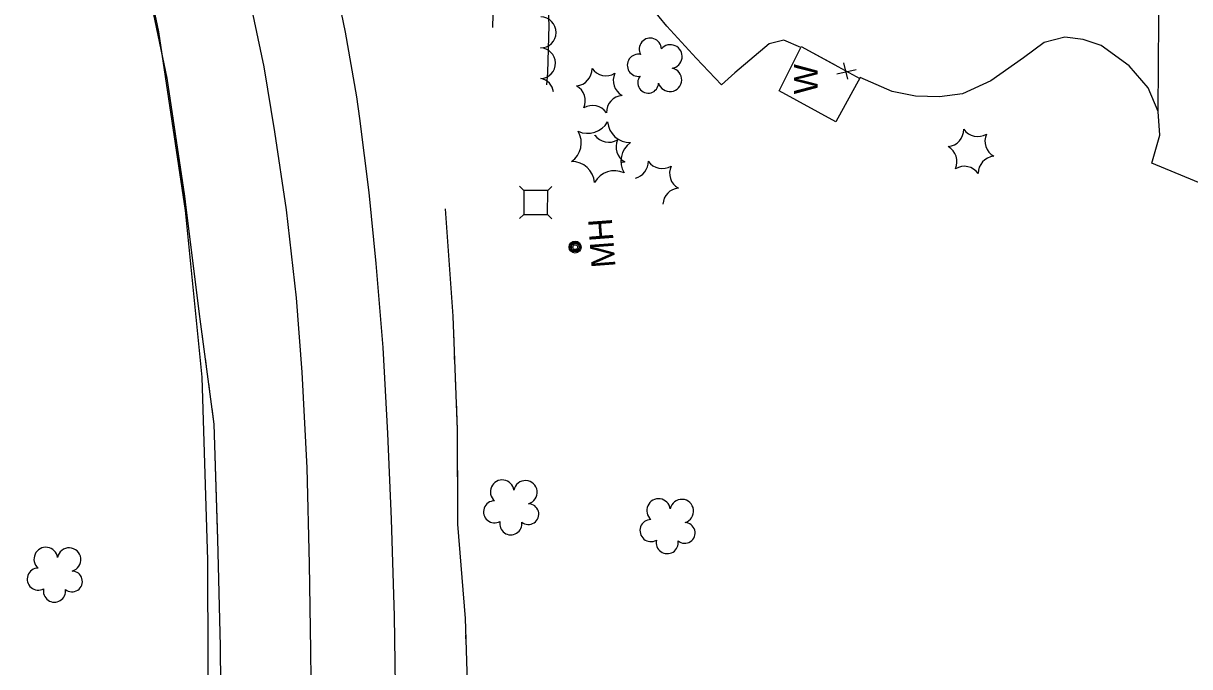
# Model space of a CAD drawing. Extents: x 588843 to 2552415, y 180129 to 269402.
# Drawn here: x 592645.4 to 592938.7, y 185379 to 185540.7 of the extents above; entities that cross this region are included whole.
import ezdxf

# ---------------------------------------------------------------- set-up
doc = ezdxf.new("R2010")
doc.units = 0
for name, color, linetype in [('Level 11', 7, 'Continuous'), ('Level 15', 7, 'Continuous'), ('Level 16', 7, 'Continuous'), ('Level 17', 7, 'Continuous'), ('Level 18', 7, 'Continuous'), ('Level 19', 7, 'Continuous'), ('Level 21', 7, 'Continuous')]:
    doc.layers.add(name, color=color, linetype=linetype)

msp = doc.modelspace()

# ---------------------------------------------------------------- linework, layer by layer
at = {"layer": 'Level 11'}
for points in [[(592682.83, 185624.55), (592685.37, 185616.33), (592691.06, 185596.14), (592695.65, 185577.64), (592699.18, 185561.87), (592702.55, 185545.65), (592705.87, 185529.8), (592708.57, 185513.44), (592711.52, 185493.8), (592713.98, 185471.73), (592715.44, 185453.04), (592716.73, 185429.01), (592717.3, 185404.86), (592717.6, 185383.08), (592717.87, 185360.97)], [(592714.52, 185591.15), (592716.74, 185582.43), (592719.68, 185569.74), (592723.86, 185550.74), (592726.35, 185538.51), (592729.21, 185522.23), (592729.94, 185516.79), (592732.28, 185498.17), (592734.08, 185480.38), (592735.79, 185459.25), (592736.99, 185437.63), (592737.9, 185416.06), (592738.62, 185391.71), (592738.96, 185368.33)], [(592930.73, 185518.6), (592930.88, 185541.72), (592932.35, 185581.31)], [(592967.66, 185489.58), (592953.28, 185495.79), (592944.74, 185499.08), (592929.16, 185505.6), (592931.18, 185512.58), (592930.73, 185518.6)]]:
    msp.add_lwpolyline(points, dxfattribs=at)
at = {"layer": 'Level 15'}
for p, q in [((592851.65, 185530.8), (592852.59, 185526.68)), ((592849.95, 185528.03), (592854.77, 185529.1))]:
    msp.add_line(p, q, dxfattribs=at)
for points in [[(592855.8, 185527.08), (592849.66, 185515.99), (592835.42, 185523.79), (592840.91, 185534.65)], [(592841.02, 185534.88), (592855.7, 185526.89)], [(592841.02, 185534.88), (592849.77, 185530.12)], [(592855.55, 185526.97), (592855.7, 185526.89)]]:
    msp.add_lwpolyline(points, dxfattribs=at)
at = {"layer": 'Level 16'}
for centre, radius in [((592784.16, 185484.47), 1.5), ((592784.16, 185484.48), 1.22), ((592784.17, 185484.47), 0.968), ((592784.18, 185484.45), 0.605)]:
    msp.add_circle(centre, radius, dxfattribs=at)
at = {"layer": 'Level 17'}
for points in [[(592632.26, 185711.18), (592646.89, 185673.04), (592660.35, 185629.45), (592669.4, 185585.85), (592679.43, 185538.57), (592686.09, 185493.67), (592690.29, 185451.79), (592691.76, 185405.78), (592691.87, 185353.19), (592691.53, 185306.74), (592691.13, 185249.27), (592691.18, 185196.22), (592690.64, 185132.51), (592691.01, 185060.47), (592691.33, 184985.54), (592691.73, 184963.57)], [(592840.91, 185534.65), (592836.62, 185536.46), (592832.91, 185535.56), (592824.34, 185528.32), (592820.93, 185525.28), (592814.61, 185532.01), (592807.21, 185540.03), (592801.4, 185547.18)], [(592930.73, 185518.6), (592928.21, 185524.48), (592923.45, 185530.05), (592916.41, 185535.18), (592911.84, 185536.67), (592907.25, 185537.21), (592902.08, 185535.87), (592896.85, 185532.02), (592888.69, 185526.26), (592881.52, 185523.03), (592875.79, 185522.27), (592869.71, 185522.45), (592863.89, 185523.61), (592855.8, 185527.08)]]:
    msp.add_lwpolyline(points, dxfattribs=at)
at = {"layer": 'Level 18'}
msp.add_lwpolyline([(592777.06, 185525.24), (592777.32, 185528.4), (592777.63, 185540.21), (592776.99, 185556.31), (592771.11, 185569.07), (592765.36, 185572.45), (592764.03, 185565.67), (592763.77, 185555.88), (592763.36, 185539.68)], dxfattribs=at)
for centre, radius, start, end in [((592775.47, 185538.44), 3.9, 269.5227, 89.5074), ((592803.05, 185534.25), 2.78, 1.3946, 209.1675), ((592775.29, 185530.71), 3.9, 274.05, 87.8171), ((592800.05, 185530.18), 2.78, 78.0716, 279.0826), ((592808.09, 185532.39), 2.97, 278.4237, 139.6575), ((592784.1, 185529.3), 4.3, 275.2113, 0.9762), ((592791.91, 185531.86), 4.3, 215.2113, 300.9762), ((592798.03, 185526.37), 4.3, 155.2113, 240.9762), ((592802.51, 185525.78), 2.61, 140.7797, 358.7123), ((592807.98, 185526.54), 2.97, 196.0745, 79.0477), ((592774.84, 185523.01), 3.9, 7.3949, 79.598), ((592782.4, 185521.26), 4.3, 335.2113, 60.9762), ((592796.33, 185518.32), 4.3, 95.2113, 180.9762), ((592788.52, 185515.77), 4.3, 35.2113, 120.9762), ((592787.33, 185518.79), 5.72, 244.9047, 330.6696), ((592798.02, 185516.47), 5.72, 184.9047, 270.6697), ((592779.98, 185510.68), 5.72, 304.9047, 30.6696), ((592792.62, 185515.13), 4.3, 215.2113, 300.9762), ((592784.81, 185512.58), 4.3, 359.538, 0.9762), ((592877.55, 185514.02), 4.3, 275.2113, 0.9762), ((592885.37, 185516.57), 4.3, 215.2113, 300.9762), ((592891.48, 185511.08), 4.3, 155.2113, 240.9762), ((592798.74, 185509.64), 4.3, 155.2113, 240.9762), ((592801.37, 185506.05), 5.72, 124.9047, 210.6697), ((592875.86, 185505.97), 4.3, 335.2113, 60.9762), ((592889.79, 185503.04), 4.3, 95.2113, 180.9762), ((592783.32, 185500.26), 5.72, 4.9047, 90.6696), ((592794.02, 185497.95), 5.72, 64.9047, 150.6696), ((592797.05, 185501.6), 4.3, 95.2113, 109.0946), ((592798.26, 185505.99), 4.3, 283.8729, 0.9762), ((592806.07, 185508.54), 4.3, 215.2113, 300.9762), ((592812.19, 185503.05), 4.3, 155.2113, 240.9762), ((592881.97, 185500.48), 4.3, 35.2113, 120.9762), ((592810.5, 185495.01), 4.3, 95.2113, 176.3293), ((592765.81, 185422.96), 2.97, 8.1171, 229.351), ((592771.66, 185422.81), 2.97, 285.7679, 168.7412), ((592763.92, 185417.92), 2.78, 91.088, 298.861), ((592772.4, 185417.34), 2.61, 230.4731, 88.4057), ((592805.13, 185418.23), 2.97, 8.1171, 229.351), ((592810.98, 185418.09), 2.97, 285.7679, 168.7412), ((592803.24, 185413.2), 2.78, 91.088, 298.861), ((592767.98, 185414.9), 2.78, 167.765, 8.776), ((592811.71, 185412.61), 2.61, 230.4731, 88.4057), ((592807.3, 185410.18), 2.78, 167.765, 8.776), ((592651.07, 185406.03), 2.97, 8.1171, 229.351), ((592656.92, 185405.89), 2.97, 285.7679, 168.7412), ((592649.18, 185401), 2.78, 91.088, 298.861), ((592657.66, 185400.42), 2.61, 230.4731, 88.4057), ((592653.24, 185397.98), 2.78, 167.765, 8.776)]:
    msp.add_arc(centre, radius, start, end, dxfattribs=at)
at = {"layer": 'Level 19'}
for points in [[(592669.88, 185580.03), (592676.22, 185552.24), (592681.48, 185526.97), (592686.13, 185495.83), (592689.8, 185466.32), (592693.35, 185439.93), (592694.26, 185411.01), (592694.88, 185384.05), (592695.17, 185355.33), (592695.15, 185329.11), (592694.39, 185297.99), (592694.22, 185267.58), (592695.77, 185237.77), (592695.8, 185214.29), (592694.45, 185180.8), (592695.14, 185151.71), (592695.95, 185117.24), (592697.17, 185082.17), (592696.64, 185050.99), (592697.01, 185016.27), (592697.27, 184976.07), (592697.63, 184961.39)], [(592678.79, 185539.91), (592679.22, 185537.85)], [(592680.08, 185533.72), (592680.51, 185531.65)], [(592681.37, 185527.53), (592681.48, 185526.97), (592685.91, 185497.3)], [(592685.91, 185497.3), (592686.13, 185495.83), (592689.72, 185466.97)], [(592751.49, 185494.08), (592753.38, 185467.07), (592753.4, 185466.59)], [(592751.49, 185494.08), (592753.38, 185467.07), (592754.51, 185438.53), (592754.55, 185414.82), (592756.48, 185391.1), (592757.19, 185369.77), (592756.64, 185343.45), (592756.49, 185324.83), (592756.67, 185303.32), (592756.69, 185282.2), (592756.51, 185253.92), (592756.94, 185228.01), (592757.27, 185202.26), (592758.13, 185174.85), (592757.09, 185147.23), (592757.63, 185124.45), (592758.22, 185098.02), (592757.71, 185068.51), (592757.66, 185036.74), (592758.54, 185006.67), (592757.52, 184972.51), (592758.06, 184939.09), (592758.05, 184938.8)], [(592690.27, 185462.79), (592690.55, 185460.7)], [(592753.55, 185462.79), (592753.63, 185460.89)], [(592753.78, 185457.09), (592753.85, 185455.2)], [(592691.12, 185456.52), (592691.4, 185454.43)], [(592754, 185451.4), (592754.08, 185449.5)], [(592691.96, 185450.25), (592692.24, 185448.16)], [(592754.23, 185445.7), (592754.51, 185438.53), (592754.54, 185418.15)], [(592692.81, 185443.99), (592693.35, 185439.93), (592694.19, 185413.47)], [(592754.54, 185418.15), (592754.55, 185414.82), (592756.48, 185391.1), (592756.5, 185390.67)], [(592694.19, 185413.47), (592694.26, 185411.01), (592694.88, 185384.05), (592694.89, 185382.91)], [(592756.62, 185386.88), (592756.69, 185384.98)], [(592756.81, 185381.18), (592756.88, 185379.28)]]:
    msp.add_lwpolyline(points, dxfattribs=at)
at = {"layer": 'Level 21'}
for p, q in [((592771.26, 185498.7), (592770.2, 185499.77)), ((592778.33, 185499.72), (592777.26, 185498.67)), ((592771.23, 185492.7), (592770.16, 185491.65)), ((592778.28, 185491.6), (592777.22, 185492.67))]:
    msp.add_line(p, q, dxfattribs=at)
msp.add_lwpolyline([(592777.22, 185492.67), (592777.26, 185498.67), (592771.26, 185498.7), (592771.23, 185492.7)], close=True, dxfattribs=at)

# ---------------------------------------------------------------- texts
at = {"layer": 'Level 15'}
msp.add_text('W', height=6, rotation=90, dxfattribs=at).set_placement((592845.16, 185522.9))
at = {"layer": 'Level 16'}
msp.add_text('MH', height=6, rotation=94.3488, dxfattribs=at).set_placement((592794.31, 185479.48))

doc.saveas('drawing.dxf')
